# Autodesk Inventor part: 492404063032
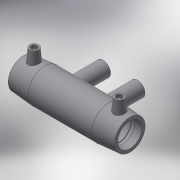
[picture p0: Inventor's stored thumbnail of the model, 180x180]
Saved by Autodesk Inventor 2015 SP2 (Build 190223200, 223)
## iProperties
Created: 2017-06
Part Number: 492404063032
Material: Generic
Description: PLASSON REDUCING TEE WITH TWO OUTLETS 63X32X32X63
Document SubType Name: Modeling
Designer: KIM
Mass: 57.3761 g
Surface Area: 241.06 cm^2
Volume: 57.3761 cm^3
Density: 1 g/cm^3
Appearance: Default
Author: KIM
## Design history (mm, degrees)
derived "492404.ipt"
feature "Solid1::492404.ipt"
tag "TaggingFeature1"
body "Solid1"
other parameters: "d0" = 213, "d1" = 63, "d2" = 82, "d3" = 58, "d4" = 42.6, "d5" = 73.8, "d6" = 59.85, "d7" = 63, "d8" = 168 deg, "d10" = 23.2, "d11" = 7.73333, "d23" = 82, "d29" = 57, "d30" = 15, "d31" = 85.2, "d34" = 5 deg, "d41" = 4, "d42" = 14, "d43" = 0, "d49" = 32, "d51" = 0, "d84" = 32, "d85" = 65, "d86" = 32.5, "d87" = 25.6, "d88" = 25.6, "d90" = 0, "d91" = 3, "d92" = 0, "d_" = 63, "L_" = 213, "L_1" = 58, "D_" = 82, "A_" = 57, "d_2" = 12, "L_2" = 65, "d_1" = 32
